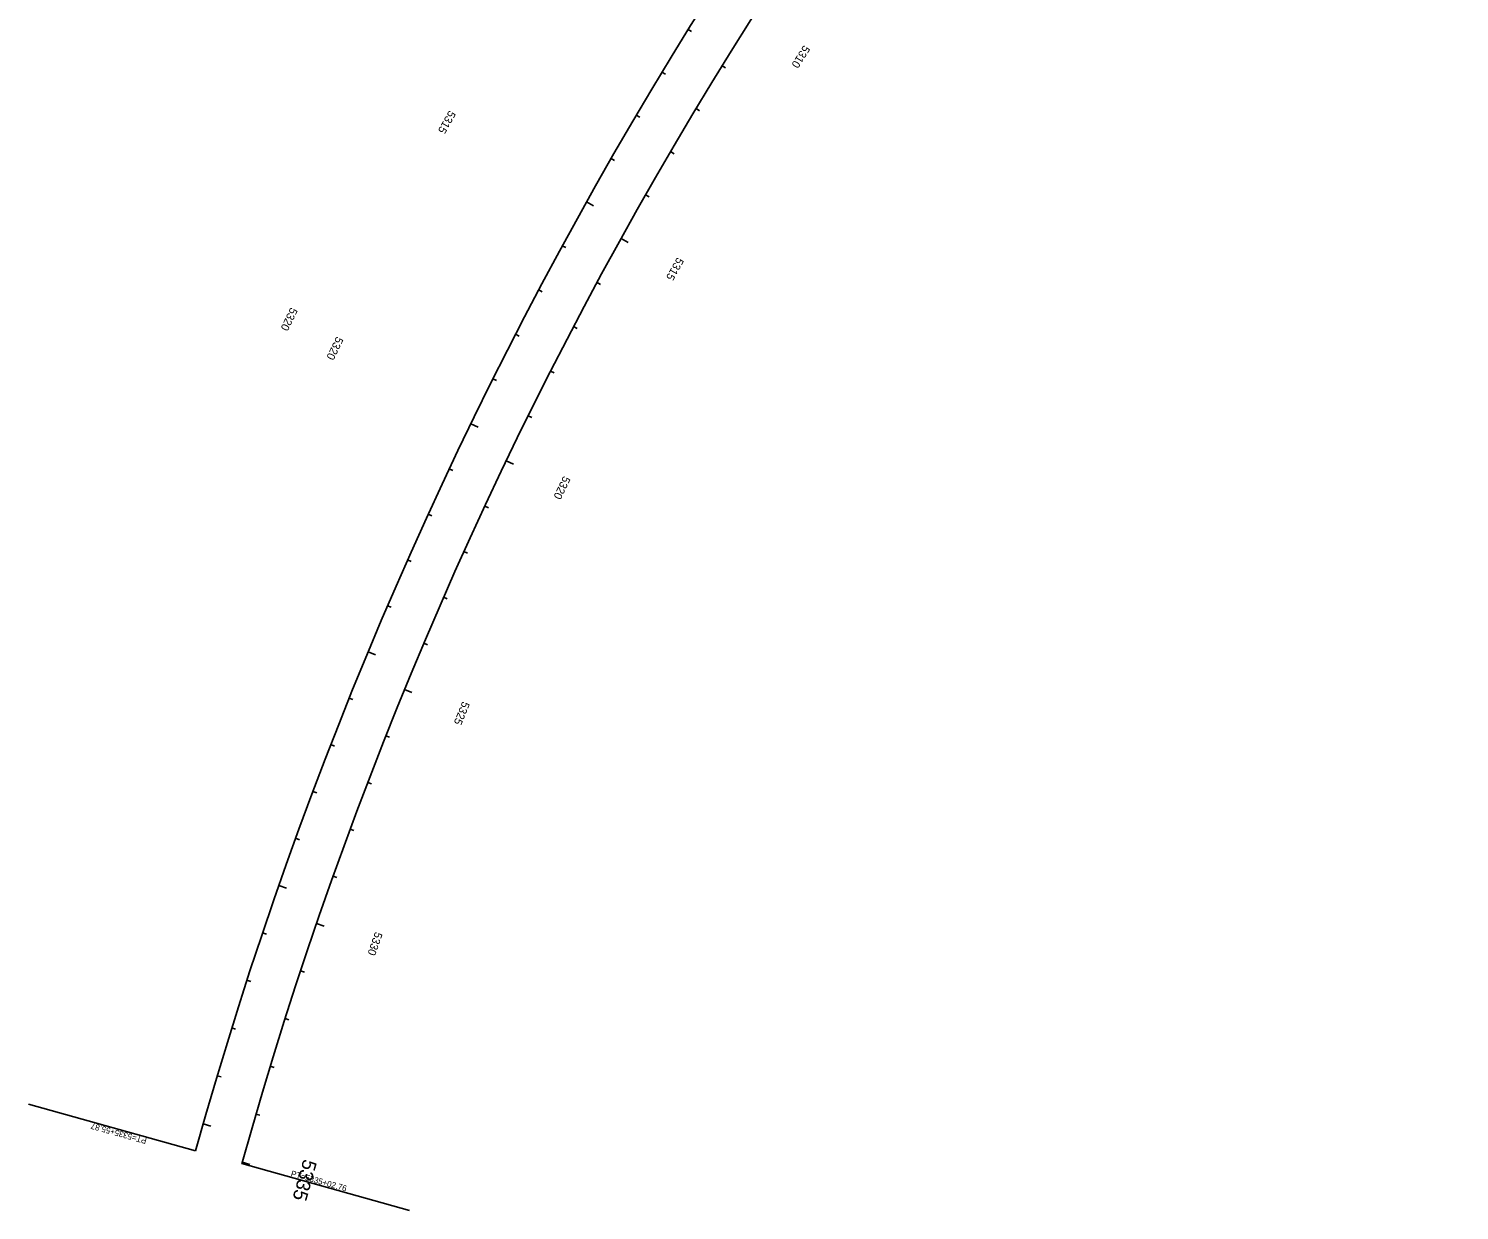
# Model space of a CAD drawing. Extents: x 2160877 to 2175861, y 601747 to 617724.
# Drawn here: x 2160877 to 2163737, y 601747 to 604108 of the extents above; entities that cross this region are included whole.
import ezdxf

# ---------------------------------------------------------------- set-up
doc = ezdxf.new("R2010")
doc.units = 0
for name, color, linetype in [('RD_HC_Cl', 7, 'Continuous'), ('RD_HC_Data', 7, 'Continuous'), ('RD_HC_Data_Tic', 7, 'Continuous'), ('RD_HC_TX_StaOther', 7, 'Continuous')]:
    doc.layers.add(name, color=color, linetype=linetype)

msp = doc.modelspace()

# ---------------------------------------------------------------- linework, layer by layer
at = {"layer": 'RD_HC_Cl'}
for radius in [8641.9, 8545.9]:
    msp.add_arc((2169535, 599544.7), radius, 132.71947, 164.41949, dxfattribs=at)
at = {"layer": 'RD_HC_Data'}
for p, q in [((2161210.6, 601865.9), (2160876.7, 601959)), ((2161303.1, 601840.1), (2161637.9, 601746.8))]:
    msp.add_line(p, q, dxfattribs=at)
at = {"layer": 'RD_HC_Data_Tic'}
for p, q in [((2162195.3, 604106.7), (2162202.1, 604102.5)), ((2162263.2, 604034.1), (2162270, 604029.9)), ((2162143, 604021.5), (2162149.8, 604017.3)), ((2162211.2, 603948.7), (2162218, 603944.5)), ((2162091.7, 603935.6), (2162098.6, 603931.6)), ((2162160.2, 603862.7), (2162167.1, 603858.6)), ((2162041.4, 603849.2), (2162048.3, 603845.2)), ((2161992.1, 603762.2), (2162006, 603754.4)), ((2162110.1, 603776.1), (2162117.1, 603772.1)), ((2161943.8, 603674.6), (2161950.8, 603670.8)), ((2162061.1, 603688.9), (2162075.1, 603681.2)), ((2161896.5, 603586.5), (2161903.6, 603582.8)), ((2162013.2, 603601.2), (2162020.2, 603597.4)), ((2161850.2, 603497.9), (2161857.4, 603494.2)), ((2161966.2, 603512.9), (2161973.3, 603509.2)), ((2161805, 603408.7), (2161812.2, 603405.1)), ((2161920.3, 603424), (2161927.4, 603420.4)), ((2161760.8, 603319), (2161775.2, 603312)), ((2161875.4, 603334.7), (2161882.6, 603331.1)), ((2161831.6, 603244.8), (2161846, 603237.9)), ((2161717.7, 603228.8), (2161724.9, 603225.4)), ((2161788.8, 603154.4), (2161796.1, 603151)), ((2161675.6, 603138.1), (2161682.8, 603134.7)), ((2161747.1, 603063.5), (2161754.4, 603060.2)), ((2161634.5, 603046.9), (2161641.8, 603043.6)), ((2161594.5, 602955.2), (2161601.9, 602952.1)), ((2161706.5, 602972.1), (2161713.8, 602968.9)), ((2161555.6, 602863.1), (2161570.4, 602857)), ((2161666.9, 602880.3), (2161674.3, 602877.2)), ((2161628.4, 602788), (2161643.2, 602781.9)), ((2161517.7, 602770.6), (2161525.1, 602767.6)), ((2161591, 602695.3), (2161598.5, 602692.3)), ((2161480.9, 602677.6), (2161488.4, 602674.7)), ((2161445.2, 602584.2), (2161452.7, 602581.4)), ((2161554.7, 602602.1), (2161562.2, 602599.2)), ((2161410.6, 602490.4), (2161418.1, 602487.6)), ((2161519.5, 602508.5), (2161527, 602505.7)), ((2161485.3, 602414.5), (2161492.9, 602411.8)), ((2161377, 602396.2), (2161392.2, 602390.9)), ((2161452.3, 602320.1), (2161467.4, 602314.9)), ((2161344.6, 602301.6), (2161352.2, 602299)), ((2161313.2, 602206.6), (2161320.9, 602204.2)), ((2161420.4, 602225.4), (2161428, 602222.9)), ((2161389.6, 602130.2), (2161397.2, 602127.8)), ((2161283, 602111.3), (2161290.6, 602108.9)), ((2161359.9, 602034.7), (2161367.5, 602032.4)), ((2161253.9, 602015.6), (2161261.5, 602013.4)), ((2161225.8, 601919.7), (2161241.2, 601915.3)), ((2161331.3, 601938.9), (2161339, 601936.7)), ((2161303.8, 601842.8), (2161319.3, 601838.5))]:
    msp.add_line(p, q, dxfattribs=at)

# ---------------------------------------------------------------- texts
at = {"layer": 'RD_HC_Data'}
for s, rotation, p in [('PT=5335+55.87', 164.4195, (2161113.8, 601890.8)), ('PT=5335+02.76', 344.4195, (2161400, 601815.2))]:
    msp.add_text(s, height=12, rotation=rotation, dxfattribs=at).set_placement(p)
at = {"layer": 'RD_HC_TX_StaOther'}
for s, height, rotation, p in [('5310', 16, 237.6399, (2162426.7, 604076.5)), ('5315', 16, 240.7891, (2161717.7, 603946)), ('5315', 16, 240.9921, (2162173.7, 603652.6)), ('5320', 16, 244.0312, (2161400.9, 603552.4)), ('5320', 16, 244.1041, (2161492.4, 603494.2)), ('5320', 16, 244.3443, (2161946.3, 603215.6)), ('5325', 16, 247.6966, (2161744.4, 602765.1)), ('5330', 16, 251.0488, (2161569.6, 602304.5)), ('5335', 28, 254.401, (2161426.5, 601850.6))]:
    msp.add_text(s, height=height, rotation=rotation, dxfattribs=at).set_placement(p)

doc.saveas('drawing.dxf')
